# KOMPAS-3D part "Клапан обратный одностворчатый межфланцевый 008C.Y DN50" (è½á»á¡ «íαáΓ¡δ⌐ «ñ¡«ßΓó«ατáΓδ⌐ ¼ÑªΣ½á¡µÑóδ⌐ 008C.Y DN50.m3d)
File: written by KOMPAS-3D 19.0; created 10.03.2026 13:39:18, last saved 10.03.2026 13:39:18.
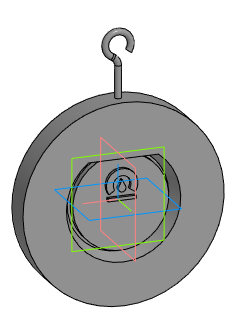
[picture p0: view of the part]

Document properties: Автор: Евгений; Полное имя файла: E:\Dendor\3D для проектировщиков\5.1 Тип 008C. Клапан обратный одностворчатый межфланцевый\stp_Клапан обратный одностворчатый межфланцевый 008C.Y\Клапан обратный одностворчатый межфланцевый 008C.Y DN50.m3d

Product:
- Part/product: Клапан обратный одностворчатый межфланцевый 008C.Y DN50

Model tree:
1. Операция без истории:1  (labels: Клапан обратный одностворчатый межфланцевый 008C.Y DN50)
